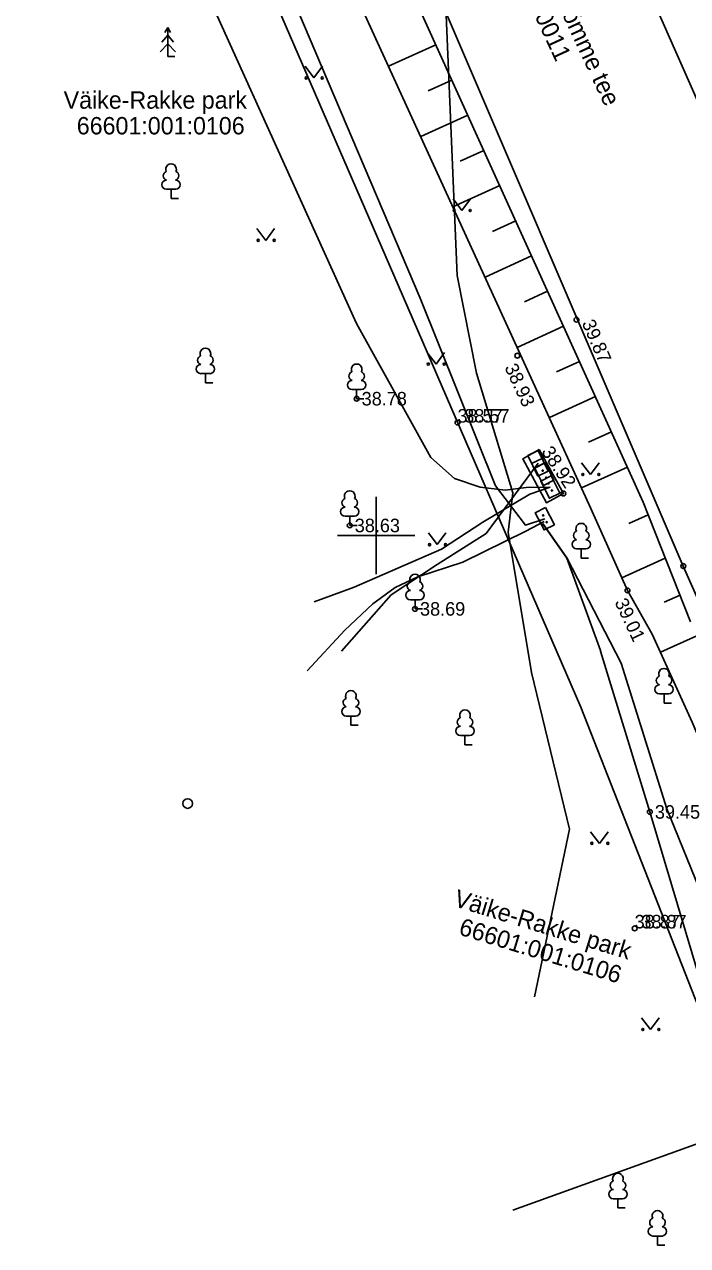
# Model space of a CAD drawing. Extents: x 627548 to 628052, y 6467984 to 6468802.
# Drawn here: x 627831.8 to 627866.1, y 6468313.2 to 6468376.5 of the extents above; entities that cross this region are included whole.
import ezdxf

# ---------------------------------------------------------------- set-up
doc = ezdxf.new("R2010")
doc.units = 0
for name, color, linetype in [('ELRAJATISMP', 7, 'Continuous'), ('HALJASTUS', 7, 'Continuous'), ('KORGUS-EH2000', 7, 'Continuous'), ('MOOTKORG-EH2000', 7, 'Continuous'), ('MOOTMPUNKT', 7, 'Continuous'), ('MPKAABEL', 7, 'Continuous'), ('PIIR', 7, 'Continuous'), ('POST', 7, 'Continuous'), ('PUU', 7, 'Continuous'), ('RAJATIS', 7, 'Continuous'), ('RELJEEF', 7, 'Continuous'), ('SIRAJATIS', 7, 'Continuous'), ('SITRASS', 7, 'Continuous'), ('TEE', 7, 'Continuous'), ('VORK', 7, 'Continuous')]:
    doc.layers.add(name, color=color, linetype=linetype)

msp = doc.modelspace()

# ---------------------------------------------------------------- linework, layer by layer
at = {"layer": 'ELRAJATISMP'}
for p, q in [((627858.393, 6468354.405), (627857.856, 6468354.143)), ((627857.856, 6468354.143), (627858.379, 6468353.07)), ((627858.916, 6468353.331), (627858.393, 6468354.405)), ((627858.058, 6468353.729), (627858.595, 6468353.99)), ((627858.177, 6468353.485), (627858.714, 6468353.746)), ((627858.379, 6468353.07), (627858.916, 6468353.331))]:
    msp.add_line(p, q, dxfattribs=at)
at = {"layer": 'HALJASTUS'}
for p, q in [((627846.314, 6468374.292), (627846.777, 6468373.686)), ((627846.777, 6468373.686), (627847.223, 6468374.292)), ((627853.983, 6468367.433), (627854.447, 6468366.826)), ((627854.447, 6468366.826), (627854.892, 6468367.433)), ((627843.825, 6468365.886), (627844.288, 6468365.279)), ((627844.288, 6468365.279), (627844.734, 6468365.886)), ((627852.639, 6468359.481), (627853.103, 6468358.874)), ((627853.103, 6468358.874), (627853.548, 6468359.481)), ((627860.645, 6468353.765), (627861.108, 6468353.158)), ((627861.108, 6468353.158), (627861.554, 6468353.765)), ((627852.707, 6468350.133), (627853.17, 6468349.526)), ((627853.17, 6468349.526), (627853.616, 6468350.133)), ((627861.113, 6468334.667), (627861.577, 6468334.061)), ((627861.577, 6468334.061), (627862.022, 6468334.667)), ((627863.758, 6468325.032), (627864.222, 6468324.426)), ((627864.222, 6468324.426), (627864.667, 6468325.032))]:
    msp.add_line(p, q, dxfattribs=at)
for centre in [(627846.376, 6468373.686), (627847.205, 6468373.686), (627854.046, 6468366.826), (627854.874, 6468366.826), (627843.887, 6468365.279), (627844.716, 6468365.279), (627852.702, 6468358.874), (627853.53, 6468358.874), (627860.707, 6468353.158), (627861.536, 6468353.158), (627852.769, 6468349.526), (627853.598, 6468349.526), (627861.176, 6468334.061), (627862.005, 6468334.061), (627863.821, 6468324.426), (627864.65, 6468324.426)]:
    msp.add_circle(centre, 0.055, dxfattribs=at)
at = {"layer": 'KORGUS-EH2000'}
for centre in [(627860.38, 6468361.171), (627857.317, 6468359.31), (627848.989, 6468357.081), (627859.701, 6468352.173), (627848.631, 6468350.521), (627865.917, 6468348.418), (627863.023, 6468347.157), (627852.014, 6468346.2), (627864.183, 6468335.69)]:
    msp.add_circle(centre, 0.125, dxfattribs=at)
at = {"layer": 'MOOTMPUNKT'}
for centre in [(627854.216, 6468355.846), (627863.396, 6468329.66)]:
    msp.add_circle(centre, 0.125, dxfattribs=at)
at = {"layer": 'MPKAABEL'}
msp.add_lwpolyline([(627858.39, 6468353.737), (627855.699, 6468350.102), (627853.16, 6468348.5), (627850.77, 6468346.922), (627848.199, 6468344.012)], dxfattribs=at)
at = {"layer": 'PIIR'}
for p, q in [((627843.3, 6468381.02), (627850.92, 6468363.47)), ((627850.92, 6468363.47), (627860.61, 6468341.12)), ((627860.61, 6468341.12), (627869.12, 6468319.4)), ((627857.089, 6468315.074), (627869.12, 6468319.4))]:
    msp.add_line(p, q, dxfattribs=at)
at = {"layer": 'POST'}
msp.add_circle((627840.233, 6468336.125), 0.25, dxfattribs=at)
at = {"layer": 'PUU'}
for p, q in [((627839.202, 6468376.295), (627839.052, 6468376.045)), ((627839.352, 6468376.045), (627839.202, 6468376.295)), ((627839.202, 6468376.295), (627839.202, 6468374.795)), ((627839.202, 6468375.895), (627838.902, 6468375.545)), ((627839.502, 6468375.545), (627839.202, 6468375.895)), ((627839.202, 6468375.445), (627838.802, 6468375.045)), ((627839.602, 6468375.045), (627839.202, 6468375.445)), ((627839.562, 6468374.795), (627839.202, 6468374.795)), ((627839.612, 6468367.923), (627839.132, 6468367.923)), ((627839.372, 6468367.448), (627839.372, 6468367.923)), ((627839.752, 6468367.448), (627839.372, 6468367.448)), ((627841.392, 6468358.378), (627840.912, 6468358.378)), ((627841.152, 6468357.903), (627841.152, 6468358.378)), ((627841.532, 6468357.903), (627841.152, 6468357.903)), ((627849.229, 6468357.556), (627848.749, 6468357.556)), ((627848.989, 6468357.081), (627848.989, 6468357.556)), ((627849.369, 6468357.081), (627848.989, 6468357.081)), ((627848.872, 6468350.996), (627848.392, 6468350.996)), ((627848.631, 6468350.521), (627848.631, 6468350.996)), ((627849.012, 6468350.521), (627848.631, 6468350.521)), ((627860.868, 6468349.307), (627860.388, 6468349.307)), ((627860.628, 6468348.832), (627860.628, 6468349.307)), ((627861.008, 6468348.832), (627860.628, 6468348.832)), ((627852.254, 6468346.675), (627851.774, 6468346.675)), ((627852.014, 6468346.2), (627852.014, 6468346.675)), ((627852.394, 6468346.2), (627852.014, 6468346.2)), ((627865.158, 6468341.797), (627864.678, 6468341.797)), ((627864.918, 6468341.322), (627864.918, 6468341.797)), ((627865.298, 6468341.322), (627864.918, 6468341.322)), ((627848.932, 6468340.651), (627848.452, 6468340.651)), ((627848.692, 6468340.176), (627848.692, 6468340.651)), ((627849.072, 6468340.176), (627848.692, 6468340.176)), ((627854.844, 6468339.646), (627854.364, 6468339.646)), ((627854.604, 6468339.171), (627854.604, 6468339.646)), ((627854.984, 6468339.171), (627854.604, 6468339.171)), ((627862.769, 6468315.663), (627862.289, 6468315.663)), ((627862.529, 6468315.188), (627862.529, 6468315.663)), ((627862.909, 6468315.188), (627862.529, 6468315.188)), ((627864.818, 6468313.736), (627864.338, 6468313.736)), ((627864.578, 6468313.261), (627864.578, 6468313.736)), ((627864.958, 6468313.261), (627864.578, 6468313.261))]:
    msp.add_line(p, q, dxfattribs=at)
for centre, radius, start, end in [((627839.372, 6468368.968), 0.277, 332.5799, 207.4201), ((627839.202, 6468368.621), 0.233, 109.02174, 253.14154), ((627839.542, 6468368.621), 0.233, 286.85082, 70.98591), ((627839.134, 6468368.161), 0.238, 90.0016, 269.3953), ((627839.609, 6468368.161), 0.238, 270.6047, 89.9984), ((627841.152, 6468359.423), 0.277, 332.5799, 207.4201), ((627840.982, 6468359.075), 0.233, 109.02174, 253.14154), ((627841.323, 6468359.075), 0.233, 286.85082, 70.98591), ((627840.915, 6468358.615), 0.238, 90.0016, 269.3953), ((627841.39, 6468358.615), 0.238, 270.6047, 89.9984), ((627848.819, 6468358.254), 0.233, 109.02174, 253.14154), ((627848.989, 6468358.601), 0.277, 332.5799, 207.4201), ((627849.159, 6468358.254), 0.233, 286.85082, 70.98591), ((627848.751, 6468357.794), 0.238, 90.0016, 269.3953), ((627849.226, 6468357.794), 0.238, 270.6047, 89.9984), ((627848.631, 6468352.041), 0.277, 332.5799, 207.4201), ((627848.461, 6468351.694), 0.233, 109.02174, 253.14154), ((627848.802, 6468351.694), 0.233, 286.85082, 70.98591), ((627848.394, 6468351.234), 0.238, 90.0016, 269.3953), ((627848.869, 6468351.234), 0.238, 270.6047, 89.9984), ((627860.458, 6468350.004), 0.233, 109.02174, 253.14154), ((627860.628, 6468350.352), 0.277, 332.5799, 207.4201), ((627860.798, 6468350.004), 0.233, 286.85082, 70.98591), ((627860.39, 6468349.544), 0.238, 90.0016, 269.3953), ((627860.865, 6468349.544), 0.238, 270.6047, 89.9984), ((627852.014, 6468347.72), 0.277, 332.5799, 207.4201), ((627851.776, 6468346.913), 0.238, 90.0016, 269.3953), ((627851.844, 6468347.373), 0.233, 109.02174, 253.14154), ((627852.184, 6468347.373), 0.233, 286.85082, 70.98591), ((627852.251, 6468346.913), 0.238, 270.6047, 89.9984), ((627864.748, 6468342.495), 0.233, 109.02174, 253.14154), ((627864.918, 6468342.842), 0.277, 332.5799, 207.4201), ((627865.089, 6468342.495), 0.233, 286.85082, 70.98591), ((627864.681, 6468342.035), 0.238, 90.0016, 269.3953), ((627865.156, 6468342.035), 0.238, 270.6047, 89.9984), ((627848.522, 6468341.349), 0.233, 109.02174, 253.14154), ((627848.692, 6468341.696), 0.277, 332.5799, 207.4201), ((627848.862, 6468341.349), 0.233, 286.85082, 70.98591), ((627848.454, 6468340.889), 0.238, 90.0016, 269.3953), ((627848.929, 6468340.889), 0.238, 270.6047, 89.9984), ((627854.604, 6468340.691), 0.277, 332.5799, 207.4201), ((627854.366, 6468339.884), 0.238, 90.0016, 269.3953), ((627854.434, 6468340.344), 0.233, 109.02174, 253.14154), ((627854.774, 6468340.344), 0.233, 286.85082, 70.98591), ((627854.841, 6468339.884), 0.238, 270.6047, 89.9984), ((627862.529, 6468316.708), 0.277, 332.5799, 207.4201), ((627862.291, 6468315.9), 0.238, 90.0016, 269.3953), ((627862.359, 6468316.36), 0.233, 109.02174, 253.14154), ((627862.699, 6468316.36), 0.233, 286.85082, 70.98591), ((627862.766, 6468315.9), 0.238, 270.6047, 89.9984), ((627864.578, 6468314.781), 0.277, 332.5799, 207.4201), ((627864.34, 6468313.974), 0.238, 90.0016, 269.3953), ((627864.408, 6468314.434), 0.233, 109.02174, 253.14154), ((627864.748, 6468314.434), 0.233, 286.85082, 70.98591), ((627864.815, 6468313.974), 0.238, 270.6047, 89.9984)]:
    msp.add_arc(centre, radius, start, end, dxfattribs=at)
at = {"layer": 'RAJATIS'}
msp.add_lwpolyline([(627858.452, 6468354.446), (627859.701, 6468352.173), (627858.826, 6468351.698), (627857.604, 6468353.971), (627858.452, 6468354.446)], dxfattribs=at)
at = {"layer": 'RELJEEF'}
for p, q in [((627853.097, 6468375.4), (627850.648, 6468374.288)), ((627853.924, 6468373.579), (627852.702, 6468373.024)), ((627854.75, 6468371.758), (627852.313, 6468370.651)), ((627855.577, 6468369.936), (627854.362, 6468369.385)), ((627856.404, 6468368.115), (627853.979, 6468367.014)), ((627857.231, 6468366.294), (627856.021, 6468365.745)), ((627858.058, 6468364.473), (627855.644, 6468363.377)), ((627858.884, 6468362.652), (627857.681, 6468362.105)), ((627859.711, 6468360.831), (627857.31, 6468359.741)), ((627860.538, 6468359.01), (627859.34, 6468358.466)), ((627861.365, 6468357.189), (627858.975, 6468356.104)), ((627862.191, 6468355.368), (627861, 6468354.826)), ((627863.018, 6468353.546), (627860.64, 6468352.467)), ((627864.104, 6468351.07), (627863.102, 6468350.618)), ((627864.976, 6468348.825), (627862.73, 6468347.813)), ((627865.746, 6468346.918), (627864.93, 6468346.551)), ((627866.62, 6468344.807), (627864.727, 6468343.953))]:
    msp.add_line(p, q, dxfattribs=at)
for points in [[(627798.462, 6468458.953), (627803.154, 6468462.558), (627806.385, 6468462.787), (627809.612, 6468460.426), (627831.39, 6468420.981), (627849.758, 6468382.754), (627863.845, 6468351.725), (627866.293, 6468345.533)], [(627863.023, 6468347.157), (627861.127, 6468351.404), (627847.089, 6468382.059), (627829.031, 6468419.236), (627807.647, 6468458.279), (627806.821, 6468459.718), (627803.902, 6468460.271), (627798.462, 6468458.953)], [(627873.347, 6468309.45), (627873.83, 6468310.241), (627877.069, 6468313.719), (627876.234, 6468317.068), (627866.378, 6468340.34), (627864.296, 6468344.897), (627863.023, 6468347.157)]]:
    msp.add_lwpolyline(points, dxfattribs=at)
at = {"layer": 'SIRAJATIS'}
for points in [[(627858.76, 6468353.757), (627859.213, 6468352.865), (627858.678, 6468352.594), (627858.225, 6468353.485)], [(627859.063, 6468353.092), (627859.516, 6468352.2), (627858.981, 6468351.929), (627858.528, 6468352.82)], [(627858.783, 6468351.448), (627859.236, 6468350.556), (627858.701, 6468350.285), (627858.248, 6468351.176)]]:
    msp.add_lwpolyline(points, close=True, dxfattribs=at)
for centre, radius in [((627858.628, 6468353.354), 0.0304), ((627858.628, 6468353.354), 0.029), ((627858.628, 6468353.354), 0.0277), ((627858.628, 6468353.354), 0.0263), ((627858.628, 6468353.354), 0.0249), ((627858.628, 6468353.354), 0.0236), ((627858.628, 6468353.354), 0.0222), ((627858.628, 6468353.354), 0.0209), ((627858.628, 6468353.354), 0.0195), ((627858.628, 6468353.354), 0.0181), ((627858.628, 6468353.354), 0.0168), ((627858.628, 6468353.354), 0.0154), ((627858.628, 6468353.354), 0.014), ((627858.628, 6468353.354), 0.0127), ((627858.628, 6468353.354), 0.0113), ((627858.628, 6468353.354), 0.00996), ((627858.628, 6468353.354), 0.0086), ((627858.628, 6468353.354), 0.00724), ((627858.628, 6468353.354), 0.00587), ((627858.628, 6468353.354), 0.00451), ((627858.628, 6468353.354), 0.00315), ((627858.628, 6468353.354), 0.00179), ((627858.628, 6468353.354), 0.000426), ((627858.81, 6468352.997), 0.0304), ((627858.81, 6468352.997), 0.029), ((627858.81, 6468352.997), 0.0277), ((627858.81, 6468352.997), 0.0263), ((627858.81, 6468352.997), 0.0249), ((627858.81, 6468352.997), 0.0236), ((627858.81, 6468352.997), 0.0222), ((627858.81, 6468352.997), 0.0209), ((627858.81, 6468352.997), 0.0195), ((627858.81, 6468352.997), 0.0181), ((627858.81, 6468352.997), 0.0168), ((627858.81, 6468352.997), 0.0154), ((627858.81, 6468352.997), 0.014), ((627858.81, 6468352.997), 0.0127), ((627858.81, 6468352.997), 0.0113), ((627858.81, 6468352.997), 0.00996), ((627858.81, 6468352.997), 0.0086), ((627858.81, 6468352.997), 0.00724), ((627858.81, 6468352.997), 0.00587), ((627858.81, 6468352.997), 0.00451), ((627858.81, 6468352.997), 0.00315), ((627858.81, 6468352.997), 0.00179), ((627858.81, 6468352.997), 0.000426), ((627858.931, 6468352.689), 0.0304), ((627858.931, 6468352.689), 0.029), ((627858.931, 6468352.689), 0.0277), ((627858.931, 6468352.689), 0.0263), ((627858.931, 6468352.689), 0.0249), ((627858.931, 6468352.689), 0.0236), ((627858.931, 6468352.689), 0.0222), ((627858.931, 6468352.689), 0.0209), ((627858.931, 6468352.689), 0.0195), ((627858.931, 6468352.689), 0.0181), ((627858.931, 6468352.689), 0.0168), ((627858.931, 6468352.689), 0.0154), ((627858.931, 6468352.689), 0.014), ((627858.931, 6468352.689), 0.0127), ((627858.931, 6468352.689), 0.0113), ((627858.931, 6468352.689), 0.00996), ((627858.931, 6468352.689), 0.0086), ((627858.931, 6468352.689), 0.00724), ((627858.931, 6468352.689), 0.00587), ((627858.931, 6468352.689), 0.00451), ((627858.931, 6468352.689), 0.00315), ((627858.931, 6468352.689), 0.00179), ((627858.931, 6468352.689), 0.000426), ((627859.113, 6468352.332), 0.0304), ((627859.113, 6468352.332), 0.029), ((627859.113, 6468352.332), 0.0277), ((627859.113, 6468352.332), 0.0263), ((627859.113, 6468352.332), 0.0249), ((627859.113, 6468352.332), 0.0236), ((627859.113, 6468352.332), 0.0222), ((627859.113, 6468352.332), 0.0209), ((627859.113, 6468352.332), 0.0195), ((627859.113, 6468352.332), 0.0181), ((627859.113, 6468352.332), 0.0168), ((627859.113, 6468352.332), 0.0154), ((627859.113, 6468352.332), 0.014), ((627859.113, 6468352.332), 0.0127), ((627859.113, 6468352.332), 0.0113), ((627859.113, 6468352.332), 0.00996), ((627859.113, 6468352.332), 0.0086), ((627859.113, 6468352.332), 0.00724), ((627859.113, 6468352.332), 0.00587), ((627859.113, 6468352.332), 0.00451), ((627859.113, 6468352.332), 0.00315), ((627859.113, 6468352.332), 0.00179), ((627859.113, 6468352.332), 0.000426), ((627858.651, 6468351.045), 0.0304), ((627858.651, 6468351.045), 0.029), ((627858.651, 6468351.045), 0.0277), ((627858.651, 6468351.045), 0.0263), ((627858.651, 6468351.045), 0.0249), ((627858.651, 6468351.045), 0.0236), ((627858.651, 6468351.045), 0.0222), ((627858.651, 6468351.045), 0.0209), ((627858.651, 6468351.045), 0.0195), ((627858.651, 6468351.045), 0.0181), ((627858.651, 6468351.045), 0.0168), ((627858.651, 6468351.045), 0.0154), ((627858.651, 6468351.045), 0.014), ((627858.651, 6468351.045), 0.0127), ((627858.651, 6468351.045), 0.0113), ((627858.651, 6468351.045), 0.00996), ((627858.651, 6468351.045), 0.0086), ((627858.651, 6468351.045), 0.00724), ((627858.651, 6468351.045), 0.00587), ((627858.651, 6468351.045), 0.00451), ((627858.651, 6468351.045), 0.00315), ((627858.651, 6468351.045), 0.00179), ((627858.651, 6468351.045), 0.000426), ((627858.833, 6468350.688), 0.0304), ((627858.833, 6468350.688), 0.029), ((627858.833, 6468350.688), 0.0277), ((627858.833, 6468350.688), 0.0263), ((627858.833, 6468350.688), 0.0249), ((627858.833, 6468350.688), 0.0236), ((627858.833, 6468350.688), 0.0222), ((627858.833, 6468350.688), 0.0209), ((627858.833, 6468350.688), 0.0195), ((627858.833, 6468350.688), 0.0181), ((627858.833, 6468350.688), 0.0168), ((627858.833, 6468350.688), 0.0154), ((627858.833, 6468350.688), 0.014), ((627858.833, 6468350.688), 0.0127), ((627858.833, 6468350.688), 0.0113), ((627858.833, 6468350.688), 0.00996), ((627858.833, 6468350.688), 0.0086), ((627858.833, 6468350.688), 0.00724), ((627858.833, 6468350.688), 0.00587), ((627858.833, 6468350.688), 0.00451), ((627858.833, 6468350.688), 0.00315), ((627858.833, 6468350.688), 0.00179), ((627858.833, 6468350.688), 0.000426)]:
    msp.add_circle(centre, radius, dxfattribs=at)
at = {"layer": 'SITRASS'}
for points in [[(627757.269, 6468529.067), (627768.1, 6468513.354), (627774.946, 6468502.943), (627783.7, 6468488.286), (627791.516, 6468476.471), (627794.222, 6468472.86), (627799.922, 6468464.28), (627804.258, 6468458.3), (627808.24, 6468452.254), (627816.937, 6468435.872), (627827.445, 6468415.491), (627836.355, 6468397.304), (627844.956, 6468379.511), (627852.286, 6468362.282), (627856.189, 6468352.574), (627857.741, 6468350.531), (627858.742, 6468350.866)], [(627858.208, 6468326.11), (627860.012, 6468334.798), (627858.052, 6468342.909), (627856.848, 6468350.174), (627857.076, 6468352.201), (627855.207, 6468358.41), (627854.195, 6468363.46), (627853.606, 6468377.354), (627852.171, 6468414.124), (627841.938, 6468447.386), (627836.234, 6468443.524)], [(627810.98, 6468412.92), (627816.008, 6468413.596), (627821.508, 6468414.106), (627822.696, 6468413.373), (627824.885, 6468409.551), (627827.286, 6468404.81), (627834.996, 6468390.373), (627839.865, 6468381.11), (627848.975, 6468360.983), (627852.832, 6468354.033), (627854.055, 6468352.951), (627855.398, 6468352.508), (627856.692, 6468352.349), (627857.78, 6468352.478), (627859.022, 6468352.51)], [(627859.022, 6468352.51), (627857.957, 6468352.139), (627855.525, 6468350.694), (627853.384, 6468349.294), (627848.859, 6468347.329), (627846.784, 6468346.562)], [(627858.708, 6468350.729), (627857.753, 6468350.229), (627854.487, 6468348.613), (627852.159, 6468347.857), (627850.981, 6468347.302), (627849.827, 6468346.471), (627848.384, 6468345.106), (627846.429, 6468343.002)], [(627895.041, 6468257.946), (627892.765, 6468263.751), (627885.861, 6468280.997), (627884.574, 6468284.991), (627881.355, 6468292.946), (627877.718, 6468303.187), (627876.72, 6468307.148), (627874.885, 6468310.594), (627872.6, 6468317.358), (627865.068, 6468335.844), (627862.702, 6468343.386), (627859.888, 6468348.841), (627858.632, 6468350.621)], [(627861.623, 6468344.046), (627859.876, 6468348.833), (627858.64, 6468350.599)], [(627893.107, 6468260.449), (627888.841, 6468271.867), (627885.53, 6468279.764), (627882.135, 6468288.441), (627879.374, 6468296.292), (627875.722, 6468305.138), (627874.264, 6468308.557), (627873.961, 6468309.445), (627871.602, 6468314.968), (627869.468, 6468319.018), (627867.454, 6468324.77), (627864.183, 6468335.69), (627861.634, 6468344.011), (627861.623, 6468344.046)]]:
    msp.add_lwpolyline(points, dxfattribs=at)
at = {"layer": 'TEE'}
for points in [[(627773.875, 6468550.47), (627771.331, 6468547.778), (627770.184, 6468544.969), (627779.724, 6468530.382), (627790.194, 6468514.89), (627795.603, 6468506.268), (627810.358, 6468482.16), (627820.252, 6468465.61), (627824.787, 6468457.176), (627842.022, 6468424.68), (627853.219, 6468402.014), (627861.194, 6468384.862), (627867.233, 6468371.168), (627873.073, 6468356.381), (627889.258, 6468318.908), (627892.446, 6468311.434), (627896.87, 6468301.517), (627899.405, 6468301.54), (627901.626, 6468302.361)], [(627850.995, 6468383.192), (627865.917, 6468348.418), (627869.848, 6468339.563), (627875.198, 6468325.862), (627878.868, 6468316.397), (627879.191, 6468315.536), (627879.247, 6468314.16), (627878.907, 6468312.752), (627878.096, 6468311.241), (627877.224, 6468310.534), (627875.866, 6468309.978), (627867.479, 6468306.988), (627868.314, 6468303.013), (627877.023, 6468305.93), (627880.299, 6468306.759), (627882.65, 6468305.874), (627884.478, 6468303.721), (627886.739, 6468296.981), (627888.125, 6468293.223), (627886.174, 6468287.898), (627882.32, 6468286.813)]]:
    msp.add_lwpolyline(points, dxfattribs=at)
at = {"layer": 'VORK'}
for p, q in [((627850, 6468352), (627850, 6468348)), ((627848, 6468350), (627852, 6468350))]:
    msp.add_line(p, q, dxfattribs=at)

# ---------------------------------------------------------------- texts
at = {"layer": 'KORGUS-EH2000'}
for s, rotation, p in [(' 39.87', 293.46996, (627860.54, 6468361.24)), (' 38.93', 295.14954, (627856.525, 6468358.939)), (' 38.92', 303.163, (627858.395, 6468354.557)), (' 39.01', 295.14954, (627862.231, 6468346.786))]:
    msp.add_text(s, height=0.7, rotation=rotation, dxfattribs=at).set_placement(p)
for s, p in [(' 38.78', (627848.989, 6468356.731)), ('38.57', (627854.566, 6468355.846)), (' 38.63', (627848.631, 6468350.171)), (' 38.69', (627852.014, 6468345.85)), (' 39.45', (627864.183, 6468335.34)), ('38.87', (627863.746, 6468329.66))]:
    msp.add_text(s, height=0.7, dxfattribs=at).set_placement(p)
at = {"layer": 'MOOTKORG-EH2000'}
for s, p in [('38.57', (627854.216, 6468355.846)), ('38.87', (627863.396, 6468329.66))]:
    msp.add_text(s, height=0.7, dxfattribs=at).set_placement(p)
at = {"layer": 'PIIR'}
for s, rotation, p in [('92 Tartu - Viljandi - Kilingi-Nõmme tee', 294.8815, (627853.314, 6468390.593)), ('66601:002:0011', 294.8815, (627855.662, 6468382.367)), ('Väike-Rakke park', 342.93348, (627853.973, 6468330.829)), ('66601:001:0106', 342.93348, (627854.231, 6468329.357))]:
    msp.add_text(s, height=0.9, rotation=rotation, dxfattribs=at).set_placement(p)
for s, p in [('Väike-Rakke park', (627833.807, 6468372.095)), ('66601:001:0106', (627834.486, 6468370.764))]:
    msp.add_text(s, height=0.9, dxfattribs=at).set_placement(p)

doc.saveas('drawing.dxf')
